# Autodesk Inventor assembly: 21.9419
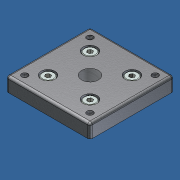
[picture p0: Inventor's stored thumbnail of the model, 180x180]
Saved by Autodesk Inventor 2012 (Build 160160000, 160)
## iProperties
Created: 2015-01
Part Number: 21.9419
Document SubType Name: Assembly
Designer: Admin
Description: Leveling Caster Mounting Plate 90
Author: Admin
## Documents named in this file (3)
- C:\Andys Backup Data\ANDY'S INVENTOR\INVENTOR LIBRARIES\PARTS LIBRARY\FEET WHEELS FLOOR FASTENING SUPPORTS\21.9419 Leveling Caster Mounting Plate 90.iam
- C:\Andys Backup Data\ANDY'S INVENTOR\INVENTOR LIBRARIES\PARTS LIBRARY\FEET WHEELS FLOOR FASTENING SUPPORTS\SUBCOMPONENTS\21.9419_1 Leveling Caster Mounting Plate 90.ipt
- C:\Andys Backup Data\ANDY'S INVENTOR\INVENTOR LIBRARIES\PARTS LIBRARY\FASTENING ELEMENTS\SCREWS CAP\21.1280 M8X22.ipt
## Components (5 placed, 2 different names)
1. 21.9419_1 Leveling Caster Mounting Plate 90:1 — Insert:1, Insert:2, Insert:3, Insert:4
2. 21.1280 M8X22:1 — Insert:1
3. 21.1280 M8X22:2 — Insert:2
4. 21.1280 M8X22:3 — Insert:3
5. 21.1280 M8X22:4 — Insert:4
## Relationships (4: Insert 4)
- Insert:1: 21.9419_1 Leveling Caster Mounting Plate 90:1 ↔ 21.1280 M8X22:1
- Insert:2: 21.9419_1 Leveling Caster Mounting Plate 90:1 ↔ 21.1280 M8X22:2
- Insert:3: 21.9419_1 Leveling Caster Mounting Plate 90:1 ↔ 21.1280 M8X22:3
- Insert:4: 21.9419_1 Leveling Caster Mounting Plate 90:1 ↔ 21.1280 M8X22:4
